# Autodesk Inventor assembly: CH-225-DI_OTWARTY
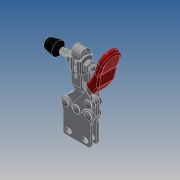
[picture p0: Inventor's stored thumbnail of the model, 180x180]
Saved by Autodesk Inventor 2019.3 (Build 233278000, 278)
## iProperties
Company: Î¢ÈíÖÐ¹ú
Created: 2013-01
Part Number: CH-225-DI_OTWARTY
Material: Ogólny
Description: STEP AP203
Document SubType Name: Assembly
Designer: CADENGINEERING4
Sending System: SolidWorks 2010
Preprocessor: SwSTEP 2.0
Title: CH-225-DI.STEP
Author: Î¢ÈíÓÃ»§
Revision Number: ÈÎºÎ
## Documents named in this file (9)
- E:\STRONA\Horizontal toggle clamp\CH-225-DI\CH-225-DI_OTWARTY.iam
- E:\STRONA\Horizontal toggle clamp\CH-225-DI\225-DI-02.ipt
- E:\STRONA\Horizontal toggle clamp\CH-225-DI\225-D-04___.ipt
- E:\STRONA\Horizontal toggle clamp\CH-225-DI\56212-01___.ipt
- E:\STRONA\Horizontal toggle clamp\CH-225-DI\225-D-05___.ipt
- E:\STRONA\Horizontal toggle clamp\CH-225-DI\FW-516___.ipt
- E:\STRONA\Horizontal toggle clamp\CH-225-DI\225-DI-01___.ipt
- E:\STRONA\Horizontal toggle clamp\CH-225-DI\225-D-03___.iam
- E:\STRONA\Horizontal toggle clamp\CH-225-DI\CH-FC-56212___.ipt
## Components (14 placed, 14 different names)
1. 225-DI-02_1 — Równoległe:1, Zestawiające:7, Zestawiające:8, Zestawiające:9, Zestawiające:21, Zestawiające:22, Zestawiające:25
2. 225-D-04____2 — Zestawiające:10, Zestawiające:11, Zestawiające:12, Zestawiające:15, Zestawiające:16
3. 56212-01____3 — Zestawiające:2, Zestawiające:5
4. 225-D-05____4 — Zestawiające:23, Zestawiające:24
5. 225-D-04____5 — Zestawiające:10, Zestawiające:11, Zestawiające:12, Zestawiające:13, Zestawiające:14
6. 225-D-05____6 — Zestawiające:26, Zestawiające:27
7. FW-516____7 — Równoległe:2, Zestawiające:4, Zestawiające:5, Zestawiające:7
8. FW-516____8 — Równoległe:1, Równoległe:2, Zestawiające:3, Zestawiające:6, Zestawiające:8
9. 225-DI-01____9 — Zestawiające:13, Zestawiające:14, Zestawiające:19, Zestawiające:20, Zestawiające:21, Zestawiające:22, Zestawiające:23, Zestawiające:24, Przejściowe:1
10. 225-D-05____10 — Zestawiające:15, Zestawiające:17, Zestawiające:18
11. 225-D-03____11 [sub-assembly] — Zestawiające:16, Zestawiające:17, Zestawiające:18, Zestawiające:25, Zestawiające:26, Zestawiające:27, Przejściowe:1
12. 56212-01____12 — Równoległe:3, Zestawiające:1, Zestawiające:6
13. 225-D-05____13 — Zestawiające:19, Zestawiające:20
14. CH-FC-56212____14 — Równoległe:3, Zestawiające:1, Zestawiające:2, Zestawiające:3, Zestawiające:4, Zestawiające:9
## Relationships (31: Mate 27, Flush 3, Transitional 1)
- Równoległe:1 [Flush]: 225-DI-02_1 ↔ FW-516____8
- Równoległe:2 [Flush]: FW-516____7 ↔ FW-516____8
- Równoległe:3 [Flush]: 56212-01____12 ↔ CH-FC-56212____14
- Zestawiające:1 [Mate]: 56212-01____12 ↔ CH-FC-56212____14
- Zestawiające:2 [Mate]: 56212-01____3 ↔ CH-FC-56212____14
- Zestawiające:3 [Mate]: FW-516____8 ↔ CH-FC-56212____14
- Zestawiające:4 [Mate]: FW-516____7 ↔ CH-FC-56212____14
- Zestawiające:5 [Mate]: 56212-01____3 ↔ FW-516____7
- Zestawiające:6 [Mate]: FW-516____8 ↔ 56212-01____12
- Zestawiające:7 [Mate]: 225-DI-02_1 ↔ FW-516____7
- Zestawiające:8 [Mate]: 225-DI-02_1 ↔ FW-516____8
- Zestawiające:9 [Mate]: 225-DI-02_1 ↔ CH-FC-56212____14
- Zestawiające:10 [Mate]: 225-D-04____2 ↔ 225-D-04____5
- Zestawiające:11 [Mate]: 225-D-04____2 ↔ 225-D-04____5
- Zestawiające:12 [Mate]: 225-D-04____2 ↔ 225-D-04____5
- Zestawiające:13 [Mate]: 225-D-04____5 ↔ 225-DI-01____9
- Zestawiające:14 [Mate]: 225-D-04____5 ↔ 225-DI-01____9
- Zestawiające:15 [Mate]: 225-D-04____2 ↔ 225-D-05____10
- Zestawiające:16 [Mate]: 225-D-04____2 ↔ 225-D-03____11
- Zestawiające:17 [Mate]: 225-D-05____10 ↔ 225-D-03____11
- Zestawiające:18 [Mate]: 225-D-05____10 ↔ 225-D-03____11
- Zestawiające:19 [Mate]: 225-DI-01____9 ↔ 225-D-05____13
- Zestawiające:20 [Mate]: 225-DI-01____9 ↔ 225-D-05____13
- Zestawiające:21 [Mate]: 225-DI-02_1 ↔ 225-DI-01____9
- Zestawiające:22 [Mate]: 225-DI-02_1 ↔ 225-DI-01____9
- Zestawiające:23 [Mate]: 225-D-05____4 ↔ 225-DI-01____9
- Zestawiające:24 [Mate]: 225-D-05____4 ↔ 225-DI-01____9
- Zestawiające:25 [Mate]: 225-DI-02_1 ↔ 225-D-03____11
- Zestawiające:26 [Mate]: 225-D-05____6 ↔ 225-D-03____11
- Zestawiające:27 [Mate]: 225-D-05____6 ↔ 225-D-03____11
- Przejściowe:1 [Transitional]: 225-DI-01____9 ↔ 225-D-03____11
